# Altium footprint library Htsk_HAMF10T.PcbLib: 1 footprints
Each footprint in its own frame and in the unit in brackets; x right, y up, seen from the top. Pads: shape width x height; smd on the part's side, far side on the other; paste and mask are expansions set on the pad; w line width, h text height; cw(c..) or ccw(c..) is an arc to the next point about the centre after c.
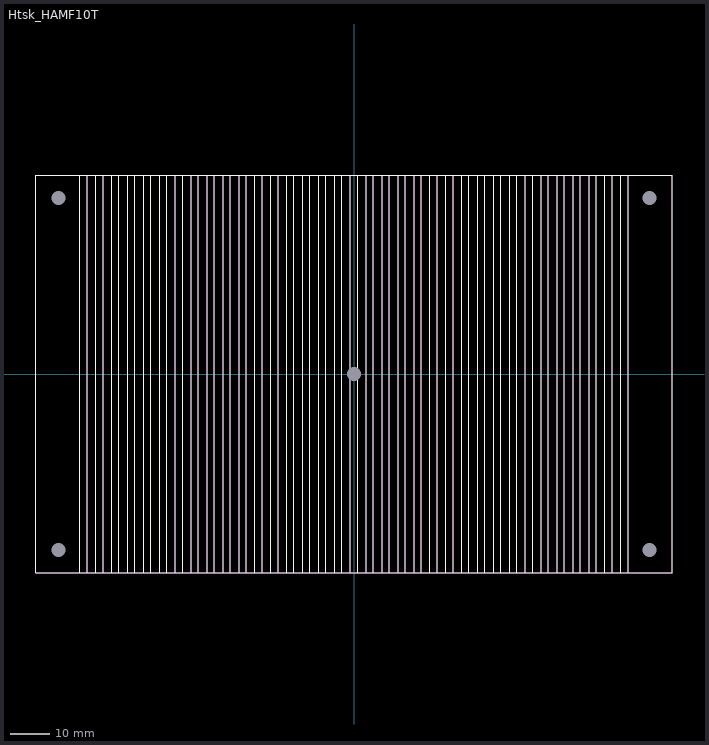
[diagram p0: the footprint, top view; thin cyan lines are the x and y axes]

## Htsk_HAMF10T [mm]
height 33.4
pads (5):
  round 0 hole 3.5 unplated: 0(-74.25,-44.25) 0(-74.25,44.25) 0(0,0) 0(74.25,-44.25) 0(74.25,44.25)
Top Overlay:
  lines w0.178: -68.9,-50 -68.9,50 ; -67.1,-50 -67.1,50 ; 3.1,-50 3.1,50 ; 4.9,-50 4.9,50 ; 7.1,-50 7.1,50 ; 8.9,-50 8.9,50 ; 11.1,-50 11.1,50 ; 12.9,-50 12.9,50 ; 15.1,-50 15.1,50 ; 16.9,-50 16.9,50 ; 19.1,-50 19.1,50 ; 20.9,-50 20.9,50 ; 23.1,-50 23.1,50 ; 24.9,-50 24.9,50 ; 27.1,-50 27.1,50 ; 28.9,-50 28.9,50 ; 31.1,-50 31.1,50 ; 32.9,-50 32.9,50 ; 35.1,-50 35.1,50 ; 36.9,-50 36.9,50 ; 39.1,-50 39.1,50 ; 40.9,-50 40.9,50 ; 43.1,-50 43.1,50 ; 44.9,-50 44.9,50 ; 47.1,-50 47.1,50 ; 48.9,-50 48.9,50 ; 51.1,-50 51.1,50 ; 52.9,-50 52.9,50 ; 55.1,-50 55.1,50 ; 56.9,-50 56.9,50 ; 59.1,-50 59.1,50 ; 60.9,-50 60.9,50 ; 63.1,-50 63.1,50 ; 64.9,-50 64.9,50 ; 67.1,-50 67.1,50 ; 68.9,-50 68.9,50 ; -80,-50 -80,50 80,50 80,-50 -80,-50 ; -64.9,-50 -64.9,50 -64.9,-50 ; -63.1,-50 -63.1,50 -63.1,-50 ; -60.9,-50 -60.9,50 -60.9,-50 ; -59.1,-50 -59.1,50 -59.1,-50 ; -56.9,-50 -56.9,50 -56.9,-50 ; -55.1,-50 -55.1,50 -55.1,-50 ; -52.9,-50 -52.9,50 -52.9,-50 ; -51.1,-50 -51.1,50 -51.1,-50 ; -48.9,-50 -48.9,50 -48.9,-50 ; -47.1,-50 -47.1,50 -47.1,-50 ; -44.9,-50 -44.9,50 -44.9,-50 ; -43.1,-50 -43.1,50 -43.1,-50 ; -40.9,-50 -40.9,50 -40.9,-50 ; -39.1,-50 -39.1,50 -39.1,-50 ; -36.9,-50 -36.9,50 -36.9,-50 ; -35.1,-50 -35.1,50 -35.1,-50 ; -32.9,-50 -32.9,50 -32.9,-50 ; -31.1,-50 -31.1,50 -31.1,-50 ; -28.9,-50 -28.9,50 -28.9,-50 ; -27.1,-50 -27.1,50 -27.1,-50 ; -24.9,-50 -24.9,50 -24.9,-50 ; -23.1,-50 -23.1,50 -23.1,-50 ; -20.9,-50 -20.9,50 -20.9,-50 ; -19.1,-50 -19.1,50 -19.1,-50 ; -16.9,-50 -16.9,50 -16.9,-50 ; -15.1,-50 -15.1,50 -15.1,-50 ; -12.9,-50 -12.9,50 -12.9,-50 ; -11.1,-50 -11.1,50 -11.1,-50 ; -8.9,-50 -8.9,50 -8.9,-50 ; -7.1,-50 -7.1,50 -7.1,-50 ; -4.9,-50 -4.9,50 -4.9,-50 ; -3.1,-50 -3.1,50 -3.1,-50 ; -0.9,-50 -0.9,50 -0.9,-50 ; 0.9,-50 0.9,50 0.9,-50
M5 Assembly Top:
  text ".Designator" at -1.524,-0.508 h1.02
M13 Component Bodies Top:
  lines w0.178: -80,-50 -80,50 80,50 80,-50 -80,-50 ; -68.9,-50 -68.9,50 -67.1,50 -67.1,-50 -68.9,-50 ; -64.9,-50 -63.1,-50 -63.1,50 -64.9,50 -64.9,-50 ; -60.9,-50 -59.1,-50 -59.1,50 -60.9,50 -60.9,-50 ; -56.9,-50 -55.1,-50 -55.1,50 -56.9,50 -56.9,-50 ; -52.9,-50 -51.1,-50 -51.1,50 -52.9,50 -52.9,-50 ; -48.9,-50 -47.1,-50 -47.1,50 -48.9,50 -48.9,-50 ; -44.9,-50 -43.1,-50 -43.1,50 -44.9,50 -44.9,-50 ; -40.9,-50 -39.1,-50 -39.1,50 -40.9,50 -40.9,-50 ; -36.9,-50 -35.1,-50 -35.1,50 -36.9,50 -36.9,-50 ; -32.9,-50 -31.1,-50 -31.1,50 -32.9,50 -32.9,-50 ; -28.9,-50 -27.1,-50 -27.1,50 -28.9,50 -28.9,-50 ; -24.9,-50 -23.1,-50 -23.1,50 -24.9,50 -24.9,-50 ; -20.9,-50 -19.1,-50 -19.1,50 -20.9,50 -20.9,-50 ; -16.9,-50 -15.1,-50 -15.1,50 -16.9,50 -16.9,-50 ; -12.9,-50 -11.1,-50 -11.1,50 -12.9,50 -12.9,-50 ; -8.9,-50 -7.1,-50 -7.1,50 -8.9,50 -8.9,-50 ; -4.9,-50 -3.1,-50 -3.1,50 -4.9,50 -4.9,-50 ; -0.9,-50 0.9,-50 0.9,50 -0.9,50 -0.9,-50 ; 3.1,-50 4.9,-50 4.9,50 3.1,50 3.1,-50 ; 7.1,-50 8.9,-50 8.9,50 7.1,50 7.1,-50 ; 11.1,-50 12.9,-50 12.9,50 11.1,50 11.1,-50 ; 15.1,-50 16.9,-50 16.9,50 15.1,50 15.1,-50 ; 19.1,-50 20.9,-50 20.9,50 19.1,50 19.1,-50 ; 23.1,-50 24.9,-50 24.9,50 23.1,50 23.1,-50 ; 27.1,-50 28.9,-50 28.9,50 27.1,50 27.1,-50 ; 31.1,-50 32.9,-50 32.9,50 31.1,50 31.1,-50 ; 35.1,-50 36.9,-50 36.9,50 35.1,50 35.1,-50 ; 39.1,-50 40.9,-50 40.9,50 39.1,50 39.1,-50 ; 43.1,-50 44.9,-50 44.9,50 43.1,50 43.1,-50 ; 47.1,-50 48.9,-50 48.9,50 47.1,50 47.1,-50 ; 51.1,-50 52.9,-50 52.9,50 51.1,50 51.1,-50 ; 55.1,-50 56.9,-50 56.9,50 55.1,50 55.1,-50 ; 59.1,-50 60.9,-50 60.9,50 59.1,50 59.1,-50 ; 63.1,-50 64.9,-50 64.9,50 63.1,50 63.1,-50 ; 67.1,-50 67.1,50 68.9,50 68.9,-50 67.1,-50
3D body: height 33.4, standoff 8, extent 67.1,-50 68.9,50
3D body: height 33.4, standoff 8, extent 63.1,-50 64.9,50
3D body: height 33.4, standoff 8, extent 59.1,-50 60.9,50
3D body: height 33.4, standoff 8, extent 55.1,-50 56.9,50
3D body: height 33.4, standoff 8, extent 51.1,-50 52.9,50
3D body: height 33.4, standoff 8, extent 47.1,-50 48.9,50
3D body: height 33.4, standoff 8, extent 43.1,-50 44.9,50
3D body: height 33.4, standoff 8, extent 39.1,-50 40.9,50
3D body: height 33.4, standoff 8, extent 35.1,-50 36.9,50
3D body: height 33.4, standoff 8, extent 31.1,-50 32.9,50
3D body: height 33.4, standoff 8, extent 27.1,-50 28.9,50
3D body: height 33.4, standoff 8, extent 23.1,-50 24.9,50
3D body: height 33.4, standoff 8, extent 19.1,-50 20.9,50
3D body: height 33.4, standoff 8, extent 15.1,-50 16.9,50
3D body: height 33.4, standoff 8, extent 11.1,-50 12.9,50
3D body: height 33.4, standoff 8, extent 7.1,-50 8.9,50
3D body: height 33.4, standoff 8, extent 3.1,-50 4.9,50
3D body: height 33.4, standoff 8, extent -0.9,-50 0.9,50
3D body: height 33.4, standoff 8, extent -4.9,-50 -3.1,50
3D body: height 33.4, standoff 8, extent -8.9,-50 -7.1,50
3D body: height 33.4, standoff 8, extent -12.9,-50 -11.1,50
3D body: height 33.4, standoff 8, extent -16.9,-50 -15.1,50
3D body: height 33.4, standoff 8, extent -20.9,-50 -19.1,50
3D body: height 33.4, standoff 8, extent -24.9,-50 -23.1,50
3D body: height 33.4, standoff 8, extent -28.9,-50 -27.1,50
3D body: height 33.4, standoff 8, extent -32.9,-50 -31.1,50
3D body: height 33.4, standoff 8, extent -36.9,-50 -35.1,50
3D body: height 33.4, standoff 8, extent -40.9,-50 -39.1,50
3D body: height 33.4, standoff 8, extent -44.9,-50 -43.1,50
3D body: height 33.4, standoff 8, extent -48.9,-50 -47.1,50
3D body: height 33.4, standoff 8, extent -52.9,-50 -51.1,50
3D body: height 33.4, standoff 8, extent -56.9,-50 -55.1,50
3D body: height 33.4, standoff 8, extent -60.9,-50 -59.1,50
3D body: height 33.4, standoff 8, extent -64.9,-50 -63.1,50
3D body: height 8, standoff 0, extent -80,-50 80,50
3D body: height 33.4, standoff 8, extent -68.9,-50 -67.1,50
